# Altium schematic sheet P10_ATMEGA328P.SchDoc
size A4; SheetNumber: 1; SheetTotal: 2
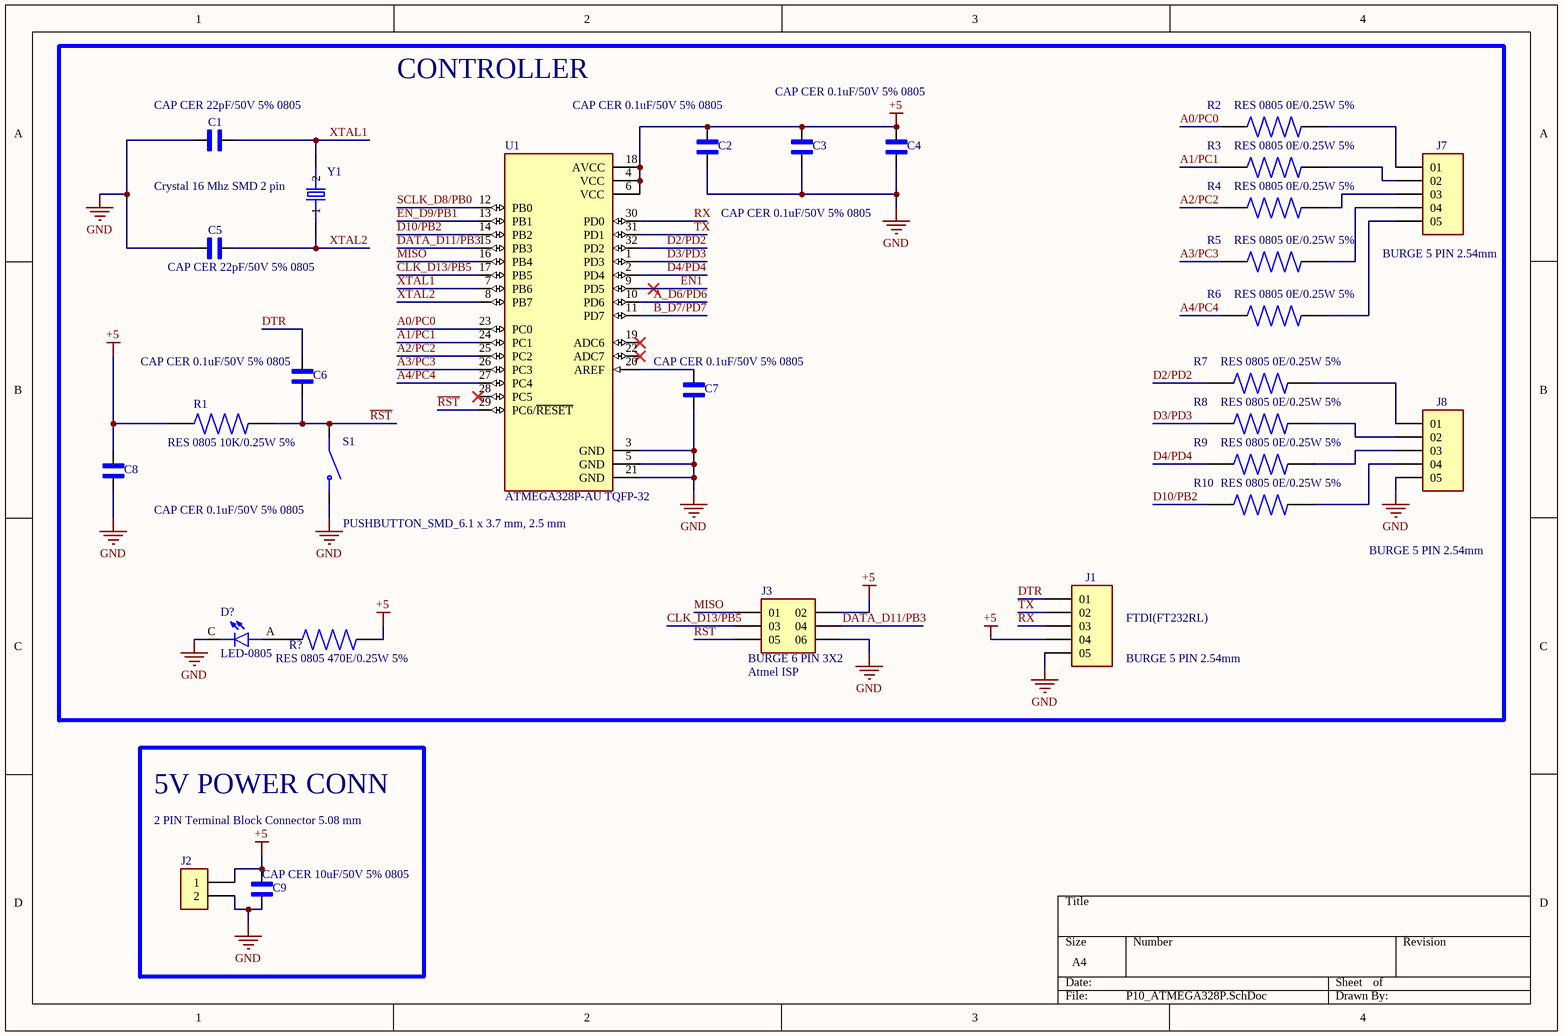
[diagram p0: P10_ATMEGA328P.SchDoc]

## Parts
C1  CAP CER 22pF/50V 5% 0805  [CAP CER 0.1uF/50V 5%]
C2  CAP CER 0.1uF/50V 5% 0805  [CAP CER 0.1uF/50V 5%]
C3  CAP CER 0.1uF/50V 5% 0805  [CAP CER 0.1uF/50V 5%]
C4  CAP CER 0.1uF/50V 5% 0805  [CAP CER 0.1uF/50V 5%]
C5  CAP CER 22pF/50V 5% 0805  [CAP CER 0.1uF/50V 5%]
C6  CAP CER 0.1uF/50V 5% 0805  [CAP CER 0.1uF/50V 5%]
C7  CAP CER 0.1uF/50V 5% 0805  [CAP CER 0.1uF/50V 5%]
C8  CAP CER 0.1uF/50V 5% 0805  [CAP CER 0.1uF/50V 5%]
C9  CAP CER 10uF/50V 5% 0805  [CAP CER 0.1uF/50V 5%]
D?  LED-0805  [LED-0805]
J1  BURGE 5 PIN 2.54mm  [BURGE 5 PIN]
J2  2 PIN Terminal Block Connector 5.08 mm  [2 PIN Terminal Block Connector 5.08 mm]
J3  BURGE 6 PIN 3X2  [BURGE 6 PIN 3X2]
J7  BURGE 5 PIN 2.54mm  [BURGE 5 PIN]
J8  BURGE 5 PIN 2.54mm  [BURGE 5 PIN]
R1  RES 0805 10K/0.25W 5%  [RES 0805 10K/0.25W 5%]
R2  RES 0805 0E/0.25W 5%  [RES 0805 10K/0.25W 5%]
R3  RES 0805 0E/0.25W 5%  [RES 0805 10K/0.25W 5%]
R4  RES 0805 0E/0.25W 5%  [RES 0805 10K/0.25W 5%]
R5  RES 0805 0E/0.25W 5%  [RES 0805 10K/0.25W 5%]
R6  RES 0805 0E/0.25W 5%  [RES 0805 10K/0.25W 5%]
R7  RES 0805 0E/0.25W 5%  [RES 0805 10K/0.25W 5%]
R8  RES 0805 0E/0.25W 5%  [RES 0805 10K/0.25W 5%]
R9  RES 0805 0E/0.25W 5%  [RES 0805 10K/0.25W 5%]
R10  RES 0805 0E/0.25W 5%  [RES 0805 10K/0.25W 5%]
R?  RES 0805 470E/0.25W 5%  [RES 0805 10K/0.25W 5%]
S1  PUSHBUTTON_SMD_6.1 x 3.7 mm, 2.5 mm  [PUSHBUTTON_SMD_6.1 x 3.7 mm, 2.5 mm]
U1  ATMEGA328P-AU TQFP-32  [ATMEGA328P-AU IC]
Y1  Crystal 16 Mhz SMD 2 pin  [Crystal 16 Mhz SMD 2 pin]

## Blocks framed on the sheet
CONTROLLER: C1-C8 D? J1 J3 J7 J8 R1-R10 R? S1 U1 Y1
5V POWER CONN: C9 J2

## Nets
+5: C2.2 C3.2 C4.2 C8.2 C9.2 J1.04 J2.1 J3.02 R1.1 R?.2 U1.4(VCC) U1.6(VCC) U1.18(AVCC)
GND: C1.1 C2.1 C3.1 C4.1 C5.1 C7.1 C8.1 C9.1 D?.C J1.05 J2.2 J3.06 J8.05 S1.2 U1.3(GND) U1.5(GND) U1.21(GND)
A0/PC0: R2.1 U1.23(PC0)
A1/PC1: R3.1 U1.24(PC1)
A2/PC2: R4.1 U1.25(PC2)
A3/PC3: R5.1 U1.26(PC3)
A4/PC4: R6.1 U1.27(PC4)
A_D6/PD6: U1.10(PD6)
B_D7/PD7: U1.11(PD7)
CLK_D13/PB5: J3.03 U1.17(PB5)
D2/PD2: R7.1 U1.32(PD2)
D3/PD3: R8.1 U1.1(PD3)
D4/PD4: R9.1 U1.2(PD4)
D10/PB2: R10.1 U1.14(PB2)
DATA_D11/PB3: J3.04 U1.15(PB3)
DTR: C6.2 J1.01
EN1: U1.9(PD5)
EN_D9/PB1: U1.13(PB1)
MISO: J3.01 U1.16(PB4)
~{RST}: C6.1 J3.05 R1.2 S1.1 U1.29(PC6/~{RESET})
RX: J1.03 U1.30(PD0)
SCLK_D8/PB0: U1.12(PB0)
TX: J1.02 U1.31(PD1)
XTAL1: C1.2 U1.7(PB6) Y1.2
XTAL2: C5.2 U1.8(PB7) Y1.1
NetC7_2: C7.2 U1.20(AREF)
NetD?_A: D?.A R?.1
NetJ7_01: J7.01 R2.2
NetJ7_02: J7.02 R3.2
NetJ7_03: J7.03 R4.2
NetJ7_04: J7.04 R5.2
NetJ7_05: J7.05 R6.2
NetJ8_01: J8.01 R7.2
NetJ8_02: J8.02 R8.2
NetJ8_03: J8.03 R9.2
NetJ8_04: J8.04 R10.2

Not connected (* = marked no-connect by the designer): U1 19(ADC6)* 22(ADC7)* 28(PC5)*

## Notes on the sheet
- FTDI(FT232RL)
- (near J3) Atmel ISP

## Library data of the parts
C1 = CAP CER 0.1uF/50V 5%: CAP CER 22pF/50V 5% Ceramic Capacitor X7R 0805 (2012 Metric); MF: Samsung; MP: CL21B104KCFNNNE
C2-C4 C6-C9 = CAP CER 0.1uF/50V 5%: CAP CER 0.1uF/50V  Ceramic Capacitor X7R 0805 (2012 Metric); MF: Samsung; MP: CL21B104KCFNNNE
C5 = CAP CER 0.1uF/50V 5%: CAP CER 22pF/50V 5%  Ceramic Capacitor X7R 0805 (2012 Metric); MF: Samsung; MP: CL21B104KCFNNNE
D? = LED-0805: Red 640nm LED Indication - Discrete 1.85V 0805 (2012 Metric) APT2012SRCPRV; MF: Kingbright
J1 J7 J8 = BURGE 5 PIN: MTSW-105-07-T-S-048 BURGE 5 PIN 2.54mm
J2 = 2 PIN Terminal Block Connector 5.08 mm: MOLEX,Screw Type, Horizontal, 5.08 Pitch, 24~12 (AWG), Terminal Block Connector, TB007-508-02BE; MF: Same Sky
J3 = BURGE 6 PIN 3X2: MTSW-103-X-X-D-X BURGE 6 PIN 3X2 2.54MM; MF: {'manufacturer': u'Samtec Inc.'}
R1-R10 R? = RES 0805 10K/0.25W 5%: RESISTOR, THICK FILM, 10K, 5%, 0805, FRESISTOR, THICK FILM, 10K, 5%, 0805, FULL REEL Product Range:PANASONIC - ERJ Series; MP: ERJ-6GEYJ103V; MF: Panasonic Electronic
S1 = PUSHBUTTON_SMD_6.1 x 3.7 mm, 2.5 mm: 6.1 x 3.7 mm, 2.5 mm Actuator Height, 260 gf, Red, Surface Mount, SPST, Tactile Switch, TS09-63-25-R-260-SMT-TR; MF: Same Sky
U1 = ATMEGA328P-AU: AVR ATMEGA328P-AU IC 8-Bit 20MHz 32KB (16K x 16) FLASH 32-TQFP (7x7); MF: Microchip
Y1 = Crystal 16 Mhz SMD 2 pin: 16 MHz Â±30ppm Crystal 20pF 60 Ohms HC-49/US FOXSDLF/128-20; MF: Fox Electronics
